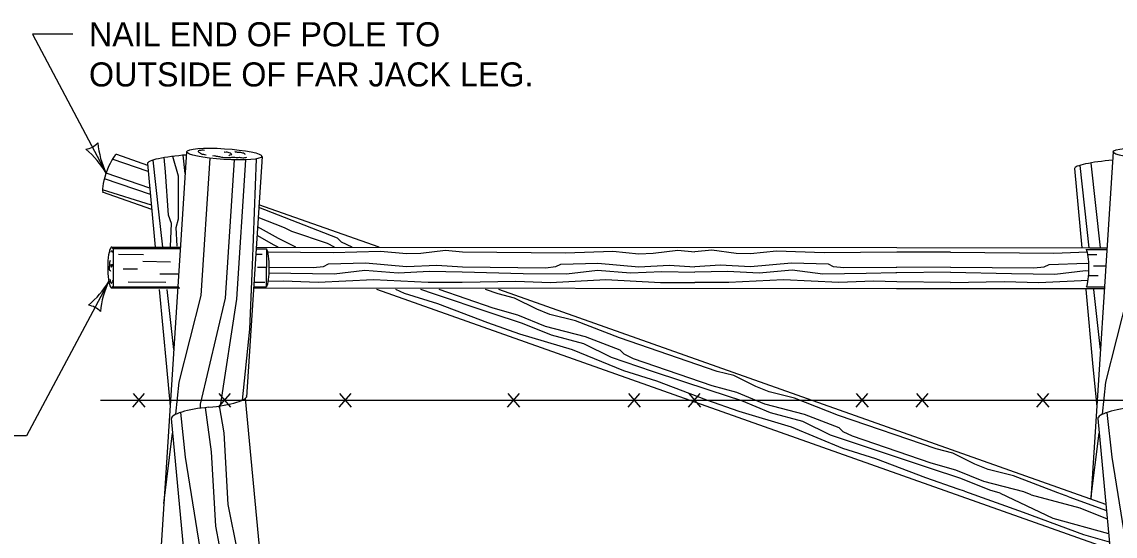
# Model space of a CAD drawing. Extents: x 49991.4 to 50021, y 49987.6 to 50011.4.
# Drawn here: x 50009.346 to 50012.065, y 49992.035 to 49993.316 of the extents above; entities that cross this region are included whole.
import ezdxf

# ---------------------------------------------------------------- set-up
doc = ezdxf.new("R2010")
doc.units = 0
for name, color, linetype in [('Level 1', 7, 'Continuous'), ('Level 2', 7, 'Continuous'), ('Level 3', 7, 'Continuous')]:
    doc.layers.add(name, color=color, linetype=linetype)

msp = doc.modelspace()

# ---------------------------------------------------------------- linework, layer by layer
at = {"layer": 'Level 1'}
for p, q in [((50009.6591, 49992.9584), (50009.5827, 49992.9854)), ((50009.7558, 49992.9922), (50009.6409, 49991.206)), ((50009.9436, 49992.9807), (50009.9046, 49992.3817)), ((50012.0604, 49992.9922), (50012.0047, 49992.1278)), ((50009.6587, 49992.963), (50009.6781, 49992.7548)), ((50011.9644, 49992.9502), (50011.9827, 49992.7533)), ((50009.6693, 49992.8487), (50009.5471, 49992.892)), ((50010.235, 49992.7545), (50009.9357, 49992.8605)), ((50009.5697, 49992.7549), (50009.7406, 49992.7548)), ((50009.5735, 49992.7511), (50009.573, 49992.6564)), ((50009.5735, 49992.7511), (50009.7404, 49992.7511)), ((50009.5861, 49992.7374), (50009.6489, 49992.7367)), ((50009.9278, 49992.7371), (50009.9438, 49992.737)), ((50009.9284, 49992.751), (50009.9553, 49992.751)), ((50009.9286, 49992.7547), (50011.5227, 49992.7536)), ((50009.955, 49992.6562), (50009.9553, 49992.751)), ((50011.5227, 49992.7536), (50012.0022, 49992.7533)), ((50011.9938, 49992.7493), (50012.0447, 49992.7492)), ((50011.9974, 49992.7364), (50012.0197, 49992.7363)), ((50012.0022, 49992.7533), (50012.045, 49992.7533)), ((50009.6472, 49992.7197), (50009.7157, 49992.7185)), ((50009.9552, 49992.7041), (50009.9324, 49992.7042)), ((50012.012, 49992.708), (50012.0421, 49992.708)), ((50009.5983, 49992.7011), (50009.634, 49992.7004)), ((50009.6892, 49992.6887), (50009.7377, 49992.6887)), ((50011.9994, 49992.6846), (50012.023, 49992.6846)), ((50009.5696, 49992.6534), (50009.7389, 49992.6534)), ((50009.573, 49992.6564), (50009.7363, 49992.6563)), ((50009.6104, 49992.6681), (50009.7046, 49992.6673)), ((50009.9241, 49992.6532), (50011.5219, 49992.6521)), ((50009.9243, 49992.6562), (50009.955, 49992.6562)), ((50009.9248, 49992.668), (50009.9503, 49992.668)), ((50011.5219, 49992.6521), (50011.5227, 49992.6521)), ((50011.5227, 49992.6521), (50012.0385, 49992.6518)), ((50011.9941, 49992.6557), (50012.0387, 49992.6557)), ((50009.6879, 49992.649), (50009.7058, 49992.4569)), ((50012.0526, 49992.0031), (50010.2289, 49992.649)), ((50012.0422, 49992.1145), (50010.5329, 49992.649)), ((50011.9924, 49992.649), (50012.0103, 49992.4569)), ((50009.7058, 49992.4569), (50009.7149, 49992.3579)), ((50012.0103, 49992.4569), (50012.0195, 49992.3579)), ((50009.6221, 49992.3561), (50009.6514, 49992.3908)), ((50009.6528, 49992.3561), (50009.6234, 49992.3908)), ((50009.8354, 49992.3561), (50009.8648, 49992.3908)), ((50009.8661, 49992.3561), (50009.8368, 49992.3908)), ((50009.9017, 49992.3783), (50010.0312, 49990.9877)), ((50010.1354, 49992.3561), (50010.1648, 49992.3908)), ((50010.1661, 49992.3561), (50010.1368, 49992.3908)), ((50010.5542, 49992.3561), (50010.5836, 49992.3908)), ((50010.5849, 49992.3561), (50010.5556, 49992.3908)), ((50010.8542, 49992.3561), (50010.8836, 49992.3908)), ((50010.8849, 49992.3561), (50010.8556, 49992.3908)), ((50011.0042, 49992.3561), (50011.0336, 49992.3908)), ((50011.0349, 49992.3561), (50011.0056, 49992.3908)), ((50011.4209, 49992.3561), (50011.4502, 49992.3908)), ((50011.4516, 49992.3561), (50011.4222, 49992.3908)), ((50011.5709, 49992.3561), (50011.6002, 49992.3908)), ((50011.6016, 49992.3561), (50011.5722, 49992.3908)), ((50011.8709, 49992.3561), (50011.9002, 49992.3908)), ((50011.9016, 49992.3561), (50011.8722, 49992.3908)), ((50009.542, 49992.3743), (50010.4473, 49992.3743)), ((50010.4473, 49992.3743), (50012.6961, 49992.3743)), ((50009.7178, 49992.3281), (50009.8443, 49990.9698)), ((50012.0223, 49992.3281), (50012.1488, 49990.9698)), ((50011.6908, 49992.1476), (50011.8363, 49992.0948)), ((50011.7793, 49992.1427), (50011.9104, 49992.0801)), ((50011.8566, 49992.1385), (50011.9772, 49992.1055)), ((50011.9505, 49992.1333), (50012.0436, 49992.0992)), ((50011.8363, 49992.0948), (50011.987, 49992.0392)), ((50011.9104, 49992.0801), (50012.0489, 49992.0422)), ((50011.9772, 49992.1055), (50012.0456, 49992.0784)), ((50011.987, 49992.0392), (50012.0509, 49992.0211))]:
    msp.add_line(p, q, dxfattribs=at)
for points in [[(50009.7038, 49992.9426), (50009.7, 49992.9777)], [(50009.7355, 49992.9313), (50009.7214, 49992.9808)], [(50009.7293, 49992.3388), (50009.7375, 49992.419), (50009.7923, 49992.6341), (50009.8143, 49992.9762)], [(50009.7524, 49992.9384), (50009.7475, 49992.9835)], [(50012.0338, 49992.3388), (50012.042, 49992.419), (50012.0969, 49992.6341), (50012.1188, 49992.9762)], [(50009.6606, 49992.943), (50009.5711, 49992.9738)], [(50009.6868, 49992.8425), (50009.6728, 49992.9715)], [(50009.7904, 49992.3538), (50009.7908, 49992.3639), (50009.8525, 49992.6279), (50009.8747, 49992.972)], [(50009.8403, 49992.3598), (50009.8809, 49992.6251), (50009.9034, 49992.9722)], [(50009.895, 49992.3743), (50009.913, 49992.5508), (50009.9198, 49992.7092), (50009.9299, 49992.9747)], [(50012.0011, 49992.7533), (50011.9788, 49992.9577)], [(50012.0288, 49992.7533), (50012.006, 49992.964)], [(50009.6659, 49992.8857), (50009.5514, 49992.925)], [(50009.6644, 49992.9017), (50009.5558, 49992.939)], [(50009.7106, 49992.8341), (50009.7038, 49992.9426)], [(50009.7356, 49992.8252), (50009.7355, 49992.9313)], [(50009.6683, 49992.8593), (50009.5464, 49992.8975)], [(50009.6964, 49992.7547), (50009.6868, 49992.8425)], [(50010.1674, 49992.7545), (50010.1414, 49992.7668), (50010.1315, 49992.7771), (50009.9353, 49992.8531)], [(50009.7186, 49992.8134), (50009.7106, 49992.8341)], [(50009.7155, 49992.7565), (50009.7186, 49992.8134)], [(50009.7299, 49992.8038), (50009.7356, 49992.8252)], [(50010.0175, 49992.7935), (50009.9994, 49992.8025), (50009.9336, 49992.8283)], [(50009.7328, 49992.7573), (50009.7299, 49992.8038)], [(50010.0276, 49992.7546), (50009.9843, 49992.7761), (50009.9322, 49992.8056)], [(50010.1241, 49992.7545), (50010.106, 49992.7635), (50010.0175, 49992.7935)], [(50009.9834, 49992.7546), (50009.9734, 49992.7596), (50009.9314, 49992.7834)], [(50009.958, 49992.7428), (50010.1203, 49992.7412), (50010.2379, 49992.745), (50010.3031, 49992.7386), (50010.3385, 49992.7398), (50010.3995, 49992.7475), (50010.4418, 49992.7434)], [(50010.4418, 49992.7434), (50010.6983, 49992.7409), (50010.8159, 49992.7447), (50010.8811, 49992.7382), (50010.9165, 49992.7395), (50010.9774, 49992.7471), (50011.0197, 49992.743)], [(50011.5227, 49992.742), (50011.3413, 49992.7405), (50011.2235, 49992.7444), (50011.1584, 49992.738), (50011.123, 49992.7393), (50011.062, 49992.7471), (50011.0197, 49992.743)], [(50011.6563, 49992.7427), (50011.5227, 49992.742)], [(50011.6563, 49992.7427), (50011.9129, 49992.7401), (50011.996, 49992.7428)], [(50009.9616, 49992.7052), (50010.0706, 49992.7041), (50010.0962, 49992.7066), (50010.1089, 49992.713), (50010.2009, 49992.7156), (50010.3031, 49992.7064), (50010.3782, 49992.7102), (50010.4418, 49992.7058)], [(50010.4418, 49992.7058), (50010.6486, 49992.7036), (50010.6741, 49992.7063), (50010.6868, 49992.7126), (50010.7789, 49992.7153), (50010.881, 49992.7061), (50010.9562, 49992.7099), (50011.0197, 49992.7054)], [(50011.5207, 49992.7043), (50011.3907, 49992.7032), (50011.3652, 49992.7058), (50011.3525, 49992.7122), (50011.2605, 49992.7149), (50011.1583, 49992.7059), (50011.0832, 49992.7098), (50011.0197, 49992.7054)], [(50011.5227, 49992.7044), (50011.5207, 49992.7043)], [(50011.6563, 49992.705), (50011.5227, 49992.7044)], [(50011.6563, 49992.705), (50011.8632, 49992.7029), (50011.8888, 49992.7054), (50011.9015, 49992.7118), (50011.9935, 49992.7145), (50011.9997, 49992.7139)], [(50009.9613, 49992.6912), (50010.0154, 49992.69), (50010.1231, 49992.6886), (50010.1995, 49992.6978), (50010.2818, 49992.6911), (50010.3598, 49992.6949), (50010.4416, 49992.693)], [(50010.4416, 49992.693), (50010.5933, 49992.6896), (50010.7011, 49992.6882), (50010.7775, 49992.6974), (50010.8597, 49992.6907), (50010.9378, 49992.6945), (50011.0197, 49992.6927)], [(50011.5196, 49992.6906), (50011.446, 49992.689), (50011.3384, 49992.6878), (50011.2619, 49992.6971), (50011.1796, 49992.6904), (50011.1016, 49992.6944), (50011.0197, 49992.6927)], [(50011.5227, 49992.6907), (50011.5196, 49992.6906)], [(50011.6563, 49992.6923), (50011.5227, 49992.6907)], [(50011.6563, 49992.6923), (50011.808, 49992.6888), (50011.9157, 49992.6875), (50011.9921, 49992.6966), (50011.9999, 49992.696)], [(50009.959, 49992.6699), (50009.997, 49992.6707), (50010.0833, 49992.6675), (50010.2209, 49992.6744), (50010.3568, 49992.6673), (50010.4416, 49992.6673)], [(50010.4416, 49992.6673), (50010.5749, 49992.6703), (50010.6613, 49992.6671), (50010.7988, 49992.674), (50010.9349, 49992.667), (50011.0197, 49992.6669)], [(50011.5227, 49992.6683), (50011.4644, 49992.6697), (50011.378, 49992.6667), (50011.2405, 49992.6738), (50011.1045, 49992.6669), (50011.0197, 49992.6669)], [(50011.6563, 49992.6666), (50011.5227, 49992.6683)], [(50011.6563, 49992.6666), (50011.7896, 49992.6695), (50011.8759, 49992.6664), (50011.9981, 49992.6725)], [(50009.7242, 49992.5), (50009.7079, 49992.649)], [(50010.5051, 49992.5665), (50010.3807, 49992.614), (50010.2981, 49992.6398), (50010.2759, 49992.649)], [(50010.5138, 49992.5908), (50010.3697, 49992.6382), (50010.3382, 49992.649)], [(50010.518, 49992.6028), (50010.3837, 49992.649)], [(50010.5306, 49992.6383), (50010.4995, 49992.649)], [(50011.0755, 49992.4453), (50010.8328, 49992.5288), (50010.7232, 49992.5716), (50010.6596, 49992.5874), (50010.6267, 49992.6005), (50010.5718, 49992.628), (50010.5306, 49992.6383)], [(50012.0287, 49992.5), (50012.0124, 49992.649)], [(50011.0628, 49992.4098), (50010.8671, 49992.4771), (50010.8439, 49992.488), (50010.8341, 49992.4984), (50010.7483, 49992.5316), (50010.6489, 49992.5571), (50010.5794, 49992.5858), (50010.518, 49992.6028)], [(50011.0585, 49992.3979), (50010.9146, 49992.4453), (50010.8126, 49992.4801), (50010.7436, 49992.5143), (50010.6639, 49992.5355), (50010.5917, 49992.5651), (50010.5138, 49992.5908)], [(50011.0501, 49992.3736), (50010.9254, 49992.421), (50010.843, 49992.4469), (50010.7157, 49992.4994), (50010.5851, 49992.5382), (50010.5051, 49992.5665)], [(50011.6203, 49992.2524), (50011.3776, 49992.3358), (50011.268, 49992.3787), (50011.2045, 49992.3944), (50011.1715, 49992.4075), (50011.1166, 49992.435), (50011.0755, 49992.4453)], [(50011.6077, 49992.2169), (50011.412, 49992.2842), (50011.3887, 49992.2951), (50011.3789, 49992.3054), (50011.2931, 49992.3386), (50011.1937, 49992.3642), (50011.1242, 49992.3929), (50011.0628, 49992.4098)], [(50011.6034, 49992.2049), (50011.4594, 49992.2524), (50011.3574, 49992.2871), (50011.2884, 49992.3212), (50011.2086, 49992.3425), (50011.1365, 49992.3722), (50011.0585, 49992.3979)], [(50009.9505, 49990.9988), (50009.8938, 49991.4307), (50009.8632, 49991.6848), (50009.8653, 49991.8677), (50009.8285, 49992.0604), (50009.8176, 49992.2455), (50009.8033, 49992.3553)], [(50009.9799, 49990.9996), (50009.913, 49991.5649), (50009.9125, 49991.6258), (50009.9245, 49991.6576), (50009.9071, 49991.8755), (50009.8594, 49992.1145), (50009.8493, 49992.2929), (50009.8373, 49992.3594)], [(50011.5949, 49992.1807), (50011.4703, 49992.2281), (50011.3878, 49992.2539), (50011.2605, 49992.3064), (50011.13, 49992.3453), (50011.0501, 49992.3736)], [(50009.8863, 49990.9899), (50009.853, 49991.3822), (50009.8235, 49991.5856), (50009.8047, 49991.9121), (50009.7533, 49992.2317), (50009.7412, 49992.3433)], [(50012.1909, 49990.9899), (50012.1576, 49991.3822), (50012.128, 49991.5856), (50012.1092, 49991.9121), (50012.0578, 49992.2317), (50012.0457, 49992.3433)], [(50009.6995, 49992.117), (50009.7212, 49992.2918)], [(50012.0053, 49992.1276), (50012.0257, 49992.2918)], [(50011.9505, 49992.1333), (50011.9225, 49992.1429), (50011.8129, 49992.1858), (50011.7493, 49992.2015), (50011.7162, 49992.2145), (50011.6615, 49992.2421), (50011.6203, 49992.2524)], [(50011.8566, 49992.1385), (50011.8379, 49992.1457), (50011.7386, 49992.1712), (50011.6691, 49992.1999), (50011.6077, 49992.2169)], [(50011.7793, 49992.1427), (50011.7535, 49992.1496), (50011.6813, 49992.1793), (50011.6034, 49992.2049)], [(50011.6908, 49992.1476), (50011.6747, 49992.1524), (50011.5949, 49992.1807)]]:
    msp.add_lwpolyline(points, dxfattribs=at)
for centre in [(50009.8497, 49992.9865), (50012.1542, 49992.9865)]:
    msp.add_ellipse(centre, major_axis=(0.0937, -0.0058), ratio=0.143064, dxfattribs=at)
for centre, major_axis, ratio, start_param, end_param in [((50009.5658, 49992.9376), (0.0169, 0.0479), 0.196346, 0.001095, 2.897749), ((50009.7522, 49992.9704), (0.0936, 0.0072), 0.143064, 1.526832, 3.157144), ((50012.058, 49992.9574), (0.0936, 0.0072), 0.143064, 1.548914, 3.140392), ((50009.5696, 49992.7042), (0, 0.0508), 0.196346, 5.894735, 9.772714), ((50009.9516, 49992.7038), (0, 0.0508), 0.196346, 3.4955, 5.901691), ((50011.9901, 49992.7022), (0, 0.0508), 0.196346, 3.558661, 5.901691), ((50009.8122, 49992.3754), (0.0932, 0.0089), 0.201992, 4.679863, 6.355951), ((50009.8113, 49992.3372), (0.0934, 0.0089), 0.201542, 1.555621, 3.157543), ((50012.1158, 49992.3372), (0.0934, 0.0089), 0.201542, 1.555621, 3.157543)]:
    msp.add_ellipse(centre, major_axis=major_axis, ratio=ratio, start_param=start_param, end_param=end_param, dxfattribs=at)
for points in [[(50009.8043, 49992.9841), (50009.7988, 49992.9853), (50009.793, 49992.9866), (50009.7887, 49992.9892), (50009.7856, 49992.9919), (50009.7862, 49992.9951), (50009.7901, 49992.996), (50009.7945, 49992.9969), (50009.8005, 49992.9966)], [(50009.8212, 49992.9825), (50009.8265, 49992.9825), (50009.8294, 49992.9815), (50009.8353, 49992.9807), (50009.8401, 49992.9796), (50009.8459, 49992.9786), (50009.8525, 49992.9776), (50009.856, 49992.9776), (50009.8656, 49992.9782), (50009.8657, 49992.9782), (50009.8718, 49992.9786), (50009.8791, 49992.9782), (50009.8898, 49992.9782), (50009.8957, 49992.9772), (50009.901, 49992.9776), (50009.9058, 49992.9789)], [(50009.8613, 49992.9833), (50009.8668, 49992.985), (50009.8683, 49992.9853), (50009.8657, 49992.9881), (50009.8647, 49992.9887), (50009.8594, 49992.9903), (50009.8542, 49992.9909), (50009.8499, 49992.9909), (50009.8493, 49992.9913)], [(50009.8756, 49992.9927), (50009.878, 49992.9919), (50009.8814, 49992.9916), (50009.8857, 49992.9909), (50009.8898, 49992.9908), (50009.895, 49992.9895), (50009.8972, 49992.9892), (50009.8996, 49992.9878), (50009.9004, 49992.9864), (50009.901, 49992.9853), (50009.901, 49992.985)], [(50009.5722, 49992.7418), (50009.5718, 49992.744), (50009.5695, 49992.7455), (50009.5687, 49992.7451), (50009.5671, 49992.7425)], [(50009.5658, 49992.7213), (50009.5641, 49992.7168), (50009.5637, 49992.7097), (50009.5645, 49992.6974), (50009.5669, 49992.6952)], [(50009.5682, 49992.7116), (50009.5686, 49992.7056), (50009.5702, 49992.7064), (50009.5702, 49992.7086), (50009.571, 49992.7123)], [(50009.5651, 49992.6755), (50009.5659, 49992.6695), (50009.5675, 49992.6665), (50009.5695, 49992.6654), (50009.5698, 49992.6661), (50009.573, 49992.6721)]]:
    msp.add_spline(points, degree=3, dxfattribs=at)
at = {"layer": 'Level 3'}
for points in [[(50009.473, 49993.2847), (50009.373, 49993.2847), (50009.5558, 49992.939)], [(50009.5623, 49992.6696), (50009.3573, 49992.2849), (50009.2073, 49992.2849)]]:
    msp.add_lwpolyline(points, dxfattribs=at)
for centre, radius, start, end in [((50009.4958, 49993.0524), 0.0548, 280.0081, 315.7305), ((50009.7564, 49993.0348), 0.2223, 185.3253, 205.5088), ((50009.3554, 49992.8201), 0.233, 30.6966, 49.9465), ((50009.3706, 49992.7822), 0.2223, 309.398, 329.5815), ((50009.7731, 49992.5703), 0.233, 154.7693, 174.0192), ((50009.502, 49992.5565), 0.0548, 44.0808, 79.8032)]:
    msp.add_arc(centre, radius, start, end, dxfattribs=at)

# ---------------------------------------------------------------- texts
at = {"layer": 'Level 2'}
for s, p in [('NAIL END OF POLE TO', (50009.513, 49993.2547)), ('OUTSIDE OF FAR JACK LEG.', (50009.513, 49993.1547))]:
    msp.add_text(s, height=0.06, dxfattribs=at).set_placement(p)

doc.saveas('drawing.dxf')
